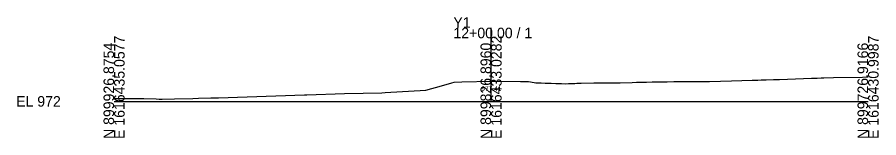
# Model space of a CAD drawing. Extents: x -26 to 203, y -10 to 2022.
# Drawn here: x -25.7 to 202.8, y 1990.3 to 2022.4 of the extents above; entities that cross this region are included whole.
import ezdxf

# ---------------------------------------------------------------- set-up
doc = ezdxf.new("R2010")
doc.units = 0
for name, color, linetype in [('Exist Cross Section Cell', 7, 'Continuous'), ('Exist XS Center Line Elevation Label', 7, 'Continuous'), ('Exist XS Ground Line', 7, 'Continuous')]:
    doc.layers.add(name, color=color, linetype=linetype)

msp = doc.modelspace()

# ---------------------------------------------------------------- linework, layer by layer
at = {"layer": 'Exist Cross Section Cell'}
for p, q in [((100, 2000), (100, 2019.6)), ((0, 2000), (100, 2000)), ((100, 2000), (200, 2000))]:
    msp.add_line(p, q, dxfattribs=at)
at = {"layer": 'Exist XS Ground Line'}
for p, q in [((198.48, 2006.48), (200, 2006.53)), ((86.86, 2004.1), (89.58, 2004.93)), ((89.58, 2004.93), (90.19, 2005.15)), ((90.19, 2005.15), (92.24, 2005.21)), ((92.24, 2005.21), (100.11, 2005.41)), ((100.11, 2005.41), (107.84, 2005.31)), ((107.84, 2005.31), (109.94, 2005.29)), ((109.94, 2005.29), (110.42, 2005.18)), ((110.42, 2005.18), (111.83, 2004.96)), ((111.83, 2004.96), (112.49, 2004.93)), ((112.49, 2004.93), (113.32, 2004.91)), ((113.32, 2004.91), (114.35, 2004.88)), ((114.35, 2004.88), (114.89, 2004.87)), ((114.89, 2004.87), (115.52, 2004.84)), ((115.52, 2004.84), (115.93, 2004.82)), ((115.93, 2004.82), (117.15, 2004.75)), ((117.15, 2004.75), (117.48, 2004.76)), ((117.48, 2004.76), (118.64, 2004.72)), ((118.64, 2004.72), (119.66, 2004.71)), ((119.66, 2004.71), (120.58, 2004.72)), ((120.58, 2004.72), (121.44, 2004.74)), ((121.44, 2004.74), (122.26, 2004.78)), ((122.26, 2004.78), (122.79, 2004.81)), ((122.79, 2004.81), (123.88, 2004.81)), ((123.88, 2004.81), (127.3, 2004.9)), ((127.3, 2004.9), (128.73, 2004.9)), ((128.73, 2004.9), (130.12, 2004.9)), ((130.12, 2004.9), (131.48, 2004.9)), ((131.48, 2004.9), (132.83, 2004.9)), ((132.83, 2004.9), (134.21, 2004.9)), ((134.21, 2004.9), (137.39, 2005.06)), ((137.39, 2005.06), (138.55, 2005.09)), ((138.55, 2005.09), (139.89, 2005.12)), ((139.89, 2005.12), (141.27, 2005.15)), ((141.27, 2005.15), (142.71, 2005.16)), ((142.71, 2005.16), (144.25, 2005.18)), ((144.25, 2005.18), (145.93, 2005.18)), ((145.93, 2005.18), (146.71, 2005.21)), ((146.71, 2005.21), (148.5, 2005.25)), ((148.5, 2005.25), (150.54, 2005.28)), ((150.54, 2005.28), (152.93, 2005.29)), ((152.93, 2005.29), (153.64, 2005.29)), ((153.64, 2005.29), (155.23, 2005.3)), ((155.23, 2005.3), (156.82, 2005.3)), ((156.82, 2005.3), (157.96, 2005.28)), ((157.96, 2005.28), (163.81, 2005.46)), ((163.81, 2005.46), (169.29, 2005.65)), ((169.29, 2005.65), (170.77, 2005.68)), ((170.77, 2005.68), (171.62, 2005.7)), ((171.62, 2005.7), (173.01, 2005.73)), ((173.01, 2005.73), (174.94, 2005.78)), ((174.94, 2005.78), (176.49, 2005.82)), ((176.49, 2005.82), (184.96, 2006.14)), ((184.96, 2006.14), (186.54, 2006.2)), ((186.54, 2006.2), (187.58, 2006.23)), ((187.58, 2006.23), (188.23, 2006.26)), ((188.23, 2006.26), (190.85, 2006.32)), ((190.85, 2006.32), (198.48, 2006.48)), ((51.16, 2001.74), (61.1, 2002.06)), ((61.1, 2002.06), (71.06, 2002.31)), ((71.06, 2002.31), (71.88, 2002.35)), ((71.88, 2002.35), (82.67, 2002.98)), ((82.67, 2002.98), (86.86, 2004.1)), ((0, 2000.75), (0.45, 2000.78)), ((0.45, 2000.78), (0.95, 2000.78)), ((0.95, 2000.78), (7.85, 2000.78)), ((7.85, 2000.78), (11.19, 2000.64)), ((11.19, 2000.64), (11.99, 2000.62)), ((11.99, 2000.62), (12.73, 2000.63)), ((12.73, 2000.63), (16.03, 2000.71)), ((16.03, 2000.71), (20.89, 2000.81)), ((20.89, 2000.81), (22.36, 2000.84)), ((22.36, 2000.84), (25.7, 2000.91)), ((25.7, 2000.91), (26.85, 2000.95)), ((26.85, 2000.95), (27.69, 2000.98)), ((27.69, 2000.98), (50.49, 2001.71)), ((50.49, 2001.71), (50.81, 2001.73)), ((50.81, 2001.73), (51.16, 2001.74))]:
    msp.add_line(p, q, dxfattribs=at)

# ---------------------------------------------------------------- texts
at = {"layer": 'Exist Cross Section Cell'}
for s, p in [('Y1', (90, 2019.6)), ('12+00.00 / 1', (90, 2016.8)), ('EL 972', (-26, 1998.6))]:
    msp.add_text(s, height=2.8, dxfattribs=at).set_placement(p)
for s, p in [('E 1616435.0577', (2.8, 1990)), ('E 1616433.0282', (102.8, 1990)), ('E 1616430.9987', (202.8, 1990)), ('N 899926.8754', (0, 1990)), ('N 899826.8960', (100, 1990)), ('N 899726.9166', (200, 1990))]:
    msp.add_text(s, height=2.8, rotation=90, dxfattribs=at).set_placement(p)
at = {"layer": 'Exist XS Center Line Elevation Label'}
msp.add_text('977.41', height=1.25, dxfattribs=at).set_placement((97.45, 2002.79))

doc.saveas('drawing.dxf')
